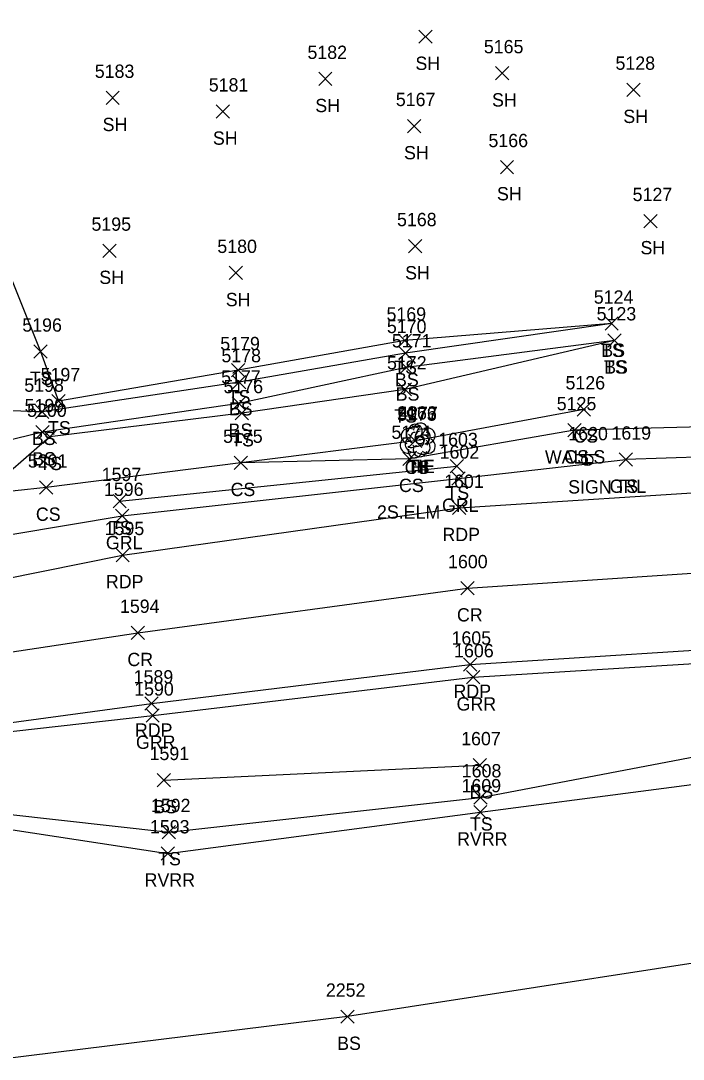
# Model space of a CAD drawing. Extents: x 1509053 to 1511576, y 400838 to 402572.
# Drawn here: x 1510102.6 to 1510202.2, y 401581.3 to 401737.4 of the extents above; entities that cross this region are included whole.
import ezdxf

# ---------------------------------------------------------------- set-up
doc = ezdxf.new("R2010")
doc.units = 0
for name, color, linetype in [('C_A', 7, 'Continuous'), ('C_I', 7, 'Continuous'), ('CBP', 7, 'Continuous'), ('L_A', 7, 'Continuous'), ('L_C', 7, 'Continuous'), ('L_I', 7, 'Continuous'), ('L_TIC', 7, 'Continuous'), ('LAWE', 7, 'Continuous'), ('LELB', 7, 'Continuous'), ('LTD', 7, 'Continuous'), ('LWS', 7, 'Continuous'), ('P_A', 7, 'Continuous'), ('P_I', 7, 'Continuous'), ('P_TIC', 7, 'Continuous'), ('PET', 7, 'Continuous'), ('PRC', 7, 'Continuous'), ('R_A', 7, 'Continuous'), ('R_I', 7, 'Continuous'), ('R_TIC', 7, 'Continuous'), ('RGR', 7, 'Continuous'), ('S_A', 7, 'Continuous'), ('S_I', 7, 'Continuous'), ('SSGN', 7, 'Continuous')]:
    doc.layers.add(name, color=color, linetype=linetype)

msp = doc.modelspace()

# ---------------------------------------------------------------- linework, layer by layer
at = {"layer": 'CBP'}
for radius in [0.625, 0.0833]:
    msp.add_circle((1510162.63, 401674.45), radius, dxfattribs=at)
at = {"layer": 'L_TIC'}
for points in [[(1510162.47, 401734.05), (1510164.47, 401736.05)], [(1510164.47, 401734.05), (1510162.47, 401736.05)], [(1510147.41, 401727.7), (1510149.41, 401729.7)], [(1510149.41, 401727.7), (1510147.41, 401729.7)], [(1510173.97, 401728.55), (1510175.97, 401730.55)], [(1510175.97, 401728.55), (1510173.97, 401730.55)], [(1510193.7, 401726.07), (1510195.7, 401728.07)], [(1510195.7, 401726.07), (1510193.7, 401728.07)], [(1510115.45, 401724.85), (1510117.45, 401726.85)], [(1510117.45, 401724.85), (1510115.45, 401726.85)], [(1510132.02, 401722.8), (1510134.02, 401724.8)], [(1510134.02, 401722.8), (1510132.02, 401724.8)], [(1510160.74, 401720.61), (1510162.74, 401722.61)], [(1510162.74, 401720.61), (1510160.74, 401722.61)], [(1510174.71, 401714.44), (1510176.71, 401716.44)], [(1510176.71, 401714.44), (1510174.71, 401716.44)], [(1510196.28, 401706.33), (1510198.28, 401708.33)], [(1510198.28, 401706.33), (1510196.28, 401708.33)], [(1510114.96, 401701.87), (1510116.96, 401703.87)], [(1510116.96, 401701.87), (1510114.96, 401703.87)], [(1510160.92, 401702.56), (1510162.92, 401704.56)], [(1510162.92, 401702.56), (1510160.92, 401704.56)], [(1510133.96, 401698.53), (1510135.96, 401700.53)], [(1510135.96, 401698.53), (1510133.96, 401700.53)], [(1510190.44, 401690.91), (1510192.44, 401692.91)], [(1510192.44, 401690.91), (1510190.44, 401692.91)], [(1510190.44, 401690.91), (1510192.44, 401692.91)], [(1510192.44, 401690.91), (1510190.44, 401692.91)], [(1510159.35, 401688.36), (1510161.35, 401690.36)], [(1510161.35, 401688.36), (1510159.35, 401690.36)], [(1510190.87, 401688.39), (1510192.87, 401690.39)], [(1510192.87, 401688.39), (1510190.87, 401690.39)], [(1510190.87, 401688.39), (1510192.87, 401690.39)], [(1510192.87, 401688.39), (1510190.87, 401690.39)], [(1510104.62, 401686.7), (1510106.62, 401688.7)], [(1510106.62, 401686.7), (1510104.62, 401688.7)], [(1510159.44, 401686.48), (1510161.44, 401688.48)], [(1510161.44, 401686.48), (1510159.44, 401688.48)], [(1510134.32, 401683.92), (1510136.32, 401685.92)], [(1510136.32, 401683.92), (1510134.32, 401685.92)], [(1510159.54, 401684.33), (1510161.54, 401686.33)], [(1510161.54, 401684.33), (1510159.54, 401686.33)], [(1510134.48, 401682.1), (1510136.48, 401684.1)], [(1510136.48, 401682.1), (1510134.48, 401684.1)], [(1510159.37, 401681.03), (1510161.37, 401683.03)], [(1510161.37, 401681.03), (1510159.37, 401683.03)], [(1510107.31, 401679.25), (1510109.31, 401681.25)], [(1510109.31, 401679.25), (1510107.31, 401681.25)], [(1510107.31, 401679.25), (1510109.31, 401681.25)], [(1510109.31, 401679.25), (1510107.31, 401681.25)], [(1510104.87, 401677.66), (1510106.87, 401679.66)], [(1510106.87, 401677.66), (1510104.87, 401679.66)], [(1510134.43, 401678.89), (1510136.43, 401680.89)], [(1510136.43, 401678.89), (1510134.43, 401680.89)], [(1510186.25, 401678.02), (1510188.25, 401680.02)], [(1510188.25, 401678.02), (1510186.25, 401680.02)], [(1510134.85, 401677.45), (1510136.85, 401679.45)], [(1510136.85, 401677.45), (1510134.85, 401679.45)], [(1510104.91, 401674.58), (1510106.91, 401676.58)], [(1510106.91, 401674.58), (1510104.91, 401676.58)], [(1510184.87, 401674.88), (1510186.87, 401676.88)], [(1510186.87, 401674.88), (1510184.87, 401676.88)], [(1510184.87, 401674.88), (1510186.87, 401676.88)], [(1510186.87, 401674.88), (1510184.87, 401676.88)], [(1510106.02, 401673.89), (1510108.02, 401675.89)], [(1510108.02, 401673.89), (1510106.02, 401675.89)], [(1510160.89, 401673.31), (1510162.89, 401675.31)], [(1510162.89, 401673.31), (1510160.89, 401675.31)], [(1510134.73, 401669.98), (1510136.73, 401671.98)], [(1510136.73, 401669.98), (1510134.73, 401671.98)], [(1510134.73, 401669.98), (1510136.73, 401671.98)], [(1510136.73, 401669.98), (1510134.73, 401671.98)], [(1510160.04, 401670.59), (1510162.04, 401672.59)], [(1510162.04, 401670.59), (1510160.04, 401672.59)], [(1510192.59, 401670.47), (1510194.59, 401672.47)], [(1510194.59, 401670.47), (1510192.59, 401672.47)], [(1510167.19, 401669.5), (1510169.19, 401671.5)], [(1510169.19, 401669.5), (1510167.19, 401671.5)], [(1510105.47, 401666.26), (1510107.47, 401668.26)], [(1510107.47, 401666.26), (1510105.47, 401668.26)], [(1510116.5, 401664.24), (1510118.49, 401666.24)], [(1510118.49, 401664.24), (1510116.5, 401666.24)], [(1510170.63, 401624.52), (1510172.63, 401626.52)], [(1510172.63, 401624.52), (1510170.63, 401626.52)], [(1510123.12, 401622.29), (1510125.12, 401624.29)], [(1510125.12, 401622.29), (1510123.12, 401624.29)], [(1510170.73, 401619.69), (1510172.73, 401621.69)], [(1510172.73, 401619.69), (1510170.73, 401621.69)], [(1510170.7, 401617.45), (1510172.7, 401619.45)], [(1510172.7, 401617.45), (1510170.7, 401619.45)], [(1510123.88, 401614.47), (1510125.88, 401616.47)], [(1510125.88, 401614.47), (1510123.88, 401616.47)], [(1510123.74, 401611.27), (1510125.74, 401613.27)], [(1510125.74, 401611.27), (1510123.74, 401613.27)], [(1510150.75, 401586.72), (1510152.75, 401588.72)], [(1510152.75, 401586.72), (1510150.75, 401588.72)]]:
    msp.add_lwpolyline(points, dxfattribs=at)
at = {"layer": 'LAWE'}
msp.add_lwpolyline([(1510071.34, 401620.03), (1510084.03, 401618.47), (1510124.74, 401612.27), (1510171.7, 401618.45), (1510222.28, 401625.1), (1510269.32, 401619.28), (1510308.65, 401601.1)], dxfattribs=at)
at = {"layer": 'LELB'}
for points in [[(1510118.99, 401826.89), (1510108.76, 401803.89), (1510097.32, 401781.18), (1510092.53, 401751.99), (1510094.65, 401729.03), (1510099.12, 401703.69), (1510105.62, 401687.7), (1510108.31, 401680.25)], [(1510431.72, 401516.61), (1510341.14, 401547.81), (1510292.56, 401583.77), (1510226.42, 401599.28), (1510151.75, 401587.72), (1510095.68, 401580.81), (1510017.56, 401603.54), (1510015.48, 401644.92), (1509989.35, 401675.01), (1509940.27, 401707.21)], [(1510191.44, 401691.91), (1510160.44, 401687.48), (1510135.48, 401683.1), (1510105.87, 401678.66), (1510096.16, 401678.94), (1510084.48, 401675.13), (1510076.18, 401668.6)], [(1510191.44, 401691.91), (1510160.35, 401689.36), (1510135.32, 401684.92), (1510108.31, 401680.25)], [(1510191.87, 401689.39), (1510160.54, 401685.33), (1510135.43, 401679.89), (1510105.91, 401675.58), (1510095.98, 401673.19), (1510085.95, 401670.54), (1510076.18, 401668.6)], [(1510191.87, 401689.39), (1510160.37, 401682.03), (1510135.85, 401678.45), (1510107.02, 401674.89), (1510097.1, 401666.29)], [(1510187.25, 401679.02), (1510161.89, 401674.31), (1510135.73, 401670.98)], [(1510185.87, 401675.88), (1510161.04, 401671.59), (1510135.73, 401670.98), (1510106.47, 401667.26), (1510097.1, 401666.29), (1510085.95, 401670.54)], [(1510211.76, 401672.09), (1510193.59, 401671.47)], [(1510117.5, 401665.24), (1510168.19, 401670.5)], [(1510171.73, 401620.69), (1510221.35, 401630.16)], [(1510124.12, 401623.29), (1510171.63, 401625.52)], [(1510071.52, 401621.36), (1510084.05, 401620.01), (1510124.88, 401615.47)], [(1510124.88, 401615.47), (1510171.73, 401620.69)]]:
    msp.add_lwpolyline(points, dxfattribs=at)
at = {"layer": 'LTD'}
for p, q in [((1510161.89, 401674.31), (1510161.89, 401674.31)), ((1510161.89, 401674.31), (1510161.89, 401674.31)), ((1510162.65, 401674.48), (1510162.65, 401674.48)), ((1510162.65, 401674.48), (1510162.65, 401674.48))]:
    msp.add_line(p, q, dxfattribs=at)
for centre in [(1510161.93, 401675.74), (1510162.7, 401675.91)]:
    msp.add_arc(centre, 1.05, 335.5272, 180.9563, dxfattribs=at)
for centre, major_axis, ratio, start_param, end_param in [((1510161.86, 401675.14), (1.21, -0.51), 0.895232, 1.570796, 4.712389), ((1510161.09, 401674.97), (1.21, -0.51), 0.895232, 1.570796, 4.712389), ((1510161.68, 401674.77), (-0.208, -0.792), 0.645439, 3.141593, 6.283185), ((1510162.44, 401674.93), (-0.208, -0.792), 0.645439, 3.141593, 6.283185), ((1510162.39, 401674.14), (-0.5, 0.667), 0.989748, 3.141593, 6.283185), ((1510162.93, 401674.89), (-1.14, -0.48), 0.949671, 1.570796, 4.712389), ((1510163.15, 401674.31), (-0.5, 0.667), 0.989748, 3.141593, 6.283185), ((1510163.69, 401675.06), (-1.14, -0.48), 0.949671, 1.570796, 4.712389), ((1510160.8, 401673.6), (0.58, -1.04), 0.959034, 3.141593, 6.283185), ((1510161.57, 401673.77), (0.58, -1.04), 0.959034, 3.141593, 6.283185), ((1510161.43, 401673.56), (-0.625, -0.083), 0.423636, 0, 3.141593), ((1510162.19, 401673.73), (-0.625, -0.083), 0.423636, 0, 3.141593), ((1510162.89, 401673.47), (-1.09, 0.79), 0.841452, 1.570796, 4.712389), ((1510163.65, 401673.64), (-1.09, 0.79), 0.841452, 1.570796, 4.712389), ((1510161.89, 401672.81), (0.26, 1.06), 0.942809, 1.570796, 4.712389), ((1510162.65, 401672.98), (0.26, 1.06), 0.942809, 1.570796, 4.712389)]:
    msp.add_ellipse(centre, major_axis=major_axis, ratio=ratio, start_param=start_param, end_param=end_param, dxfattribs=at)
at = {"layer": 'LWS'}
msp.add_lwpolyline([(1510349.81, 401679.3), (1510337.11, 401685.04), (1510331.2, 401679.18), (1510316.95, 401676.48), (1510297.59, 401679.14), (1510269.51, 401678.15), (1510244.84, 401677.73), (1510225.49, 401677.12), (1510218.49, 401676.76), (1510185.87, 401675.88)], dxfattribs=at)
at = {"layer": 'P_TIC'}
for points in [[(1510167.51, 401663.21), (1510169.51, 401665.21)], [(1510169.51, 401663.21), (1510167.51, 401665.21)], [(1510116.95, 401656.12), (1510118.95, 401658.12)], [(1510118.95, 401656.12), (1510116.95, 401658.12)], [(1510168.76, 401651.13), (1510170.76, 401653.13)], [(1510170.76, 401651.13), (1510168.76, 401653.13)], [(1510119.23, 401644.42), (1510121.23, 401646.42)], [(1510121.23, 401644.42), (1510119.23, 401646.42)], [(1510169.19, 401639.65), (1510171.19, 401641.65)], [(1510171.19, 401639.65), (1510169.19, 401641.65)], [(1510121.3, 401633.81), (1510123.3, 401635.81)], [(1510123.3, 401633.81), (1510121.3, 401635.81)]]:
    msp.add_lwpolyline(points, dxfattribs=at)
at = {"layer": 'PET'}
for points in [[(1510068.52, 401654.76), (1510069.7, 401647.38), (1510117.95, 401657.12), (1510168.51, 401664.21), (1510212.05, 401667), (1510220.39, 401667.36), (1510271.44, 401667.79), (1510321.9, 401665.44), (1510371.76, 401662.64), (1510420.35, 401661.34), (1510470.43, 401662.43), (1510520.33, 401664.72), (1510570.63, 401667.06), (1510593.1, 401669.05), (1510621.58, 401670.53), (1510656.11, 401672.66)], [(1510069.7, 401647.38), (1510070.82, 401637.95), (1510072.41, 401628.04), (1510122.3, 401634.81), (1510170.19, 401640.65), (1510220.23, 401643.86), (1510269.72, 401644.29), (1510320.63, 401641.42), (1510370.24, 401637.87), (1510421.73, 401637.03), (1510472.3, 401638.25), (1510523.24, 401640.81), (1510571.7, 401643.53), (1510622.45, 401646.41), (1510672.72, 401649.13), (1510722.86, 401651.91), (1510723.41, 401651.94), (1510773.15, 401654.37), (1510822.4, 401657.74), (1510872.35, 401660.8), (1510922.85, 401663.95), (1510967.23, 401666.49), (1511034, 401670.65), (1511071.49, 401673.22)]]:
    msp.add_lwpolyline(points, dxfattribs=at)
at = {"layer": 'PRC'}
msp.add_lwpolyline([(1510070.82, 401637.95), (1510120.23, 401645.42), (1510169.76, 401652.13), (1510220.07, 401655.52), (1510220.14, 401655.43), (1510270.51, 401655.53), (1510320.84, 401653.34), (1510371.03, 401650.53), (1510421.26, 401649.11), (1510471.33, 401650.1), (1510521.34, 401652.38), (1510571.58, 401655.12), (1510621.67, 401657.75), (1510671.66, 401660.66), (1510722.15, 401663.46), (1510772.15, 401666.42), (1510822.28, 401669.1), (1510872.26, 401671.98), (1510872.29, 401672.01), (1510922.21, 401674.96), (1510971.31, 401678.08), (1511022.51, 401681.61), (1511070.2, 401684.98)], dxfattribs=at)
at = {"layer": 'R_TIC'}
for points in [[(1510192.59, 401670.47), (1510194.59, 401672.47)], [(1510194.59, 401670.47), (1510192.59, 401672.47)], [(1510167.4, 401667.61), (1510169.4, 401669.61)], [(1510169.4, 401667.61), (1510167.4, 401669.61)], [(1510116.88, 401662), (1510118.88, 401664)], [(1510118.88, 401662), (1510116.88, 401664)], [(1510169.64, 401637.74), (1510171.64, 401639.74)], [(1510171.64, 401637.74), (1510169.64, 401639.74)], [(1510121.46, 401631.98), (1510123.46, 401633.98)], [(1510123.46, 401631.98), (1510121.46, 401633.98)]]:
    msp.add_lwpolyline(points, dxfattribs=at)
at = {"layer": 'RGR'}
for points in [[(1510068.52, 401654.76), (1510117.89, 401663), (1510168.4, 401668.61), (1510193.59, 401671.47)], [(1510073.99, 401627.51), (1510122.46, 401632.98), (1510170.64, 401638.74), (1510220.08, 401641.84), (1510269.6, 401641.85), (1510311.11, 401639.49), (1510334.05, 401636.42), (1510370.16, 401634.91), (1510403.15, 401632.59)]]:
    msp.add_lwpolyline(points, dxfattribs=at)
at = {"layer": 'SSGN'}
for p, q in [((1510186.12, 401672.23), (1510189.45, 401672.23)), ((1510187.77, 401671.39), (1510187.77, 401671.39))]:
    msp.add_line(p, q, dxfattribs=at)
msp.add_circle((1510187.77, 401671.39), 0.833, dxfattribs=at)

# ---------------------------------------------------------------- texts
at = {"layer": 'C_A'}
msp.add_text('TIE', height=2, dxfattribs=at).set_placement((1510160.71, 401669.45))
at = {"layer": 'C_I'}
msp.add_text('4277', height=2, dxfattribs=at).set_placement((1510159.37, 401677.45))
at = {"layer": 'L_A'}
for s, p in [('SH', (1510161.95, 401730.05)), ('SH', (1510173.46, 401724.55)), ('SH', (1510146.9, 401723.7)), ('SH', (1510193.19, 401722.07)), ('SH', (1510114.94, 401720.85)), ('SH', (1510131.51, 401718.8)), ('SH', (1510160.23, 401716.61)), ('SH', (1510174.2, 401710.44)), ('SH', (1510195.77, 401702.33)), ('SH', (1510114.44, 401697.87)), ('SH', (1510160.4, 401698.56)), ('SH', (1510133.45, 401694.53)), ('TS', (1510189.85, 401686.91)), ('BS', (1510189.88, 401686.91)), ('TS', (1510158.76, 401684.36)), ('TS', (1510190.28, 401684.39)), ('BS', (1510190.31, 401684.39)), ('TS', (1510104.03, 401682.7)), ('BS', (1510158.88, 401682.48)), ('TS', (1510133.73, 401679.92)), ('BS', (1510158.98, 401680.33)), ('BS', (1510133.92, 401678.1)), ('TS', (1510158.78, 401677.03)), ('TS', (1510106.72, 401675.25)), ('TS', (1510106.72, 401675.25)), ('BS', (1510133.87, 401674.89)), ('BS', (1510104.31, 401673.66)), ('TS', (1510134.26, 401673.45)), ('CS', (1510185.69, 401674.02)), ('BS', (1510104.35, 401670.58)), ('TS', (1510105.42, 401669.89)), ('WALLS', (1510181.41, 401670.88)), ('CS', (1510184.31, 401670.88)), ('CS', (1510160.33, 401669.31)), ('H', (1510161.32, 401669.31)), ('H', (1510162.08, 401669.48)), ('CS', (1510134.17, 401665.98)), ('CS', (1510134.17, 401665.98)), ('CS', (1510159.48, 401666.59)), ('TS', (1510166.6, 401665.5)), ('TS', (1510192, 401666.47)), ('CS', (1510104.91, 401662.26)), ('TS', (1510115.9, 401660.24)), ('BS', (1510170.07, 401620.52)), ('BS', (1510122.56, 401618.29)), ('TS', (1510170.14, 401615.69)), ('RVRR', (1510168.21, 401613.45)), ('TS', (1510123.29, 401610.47)), ('RVRR', (1510121.25, 401607.27)), ('BS', (1510150.19, 401582.72))]:
    msp.add_text(s, height=2, dxfattribs=at).set_placement(p)
at = {"layer": 'L_C'}
msp.add_text('2S.ELM', height=2, dxfattribs=at).set_placement((1510156.17, 401662.59))
at = {"layer": 'L_I'}
for s, p in [('5165', (1510172.23, 401732.55)), ('5182', (1510145.72, 401731.7)), ('5128', (1510192.01, 401730.07)), ('5183', (1510113.76, 401728.85)), ('5181', (1510130.89, 401726.8)), ('5167', (1510159, 401724.61)), ('5166', (1510172.92, 401718.44)), ('5127', (1510194.59, 401710.33)), ('5195', (1510113.26, 401705.87)), ('5168', (1510159.18, 401706.56)), ('5180', (1510132.18, 401702.53)), ('5124', (1510188.75, 401694.91)), ('5124', (1510188.75, 401694.91)), ('5169', (1510157.6, 401692.36)), ('5123', (1510189.18, 401692.39)), ('5123', (1510189.18, 401692.39)), ('5196', (1510102.87, 401690.7)), ('5170', (1510157.66, 401690.48)), ('5179', (1510132.62, 401687.92)), ('5171', (1510158.41, 401688.33)), ('5178', (1510132.79, 401686.1)), ('5172', (1510157.68, 401685.03)), ('5197', (1510105.62, 401683.25)), ('5197', (1510105.62, 401683.25)), ('5177', (1510132.74, 401682.89)), ('5198', (1510103.17, 401681.66)), ('5176', (1510133.1, 401681.45)), ('5126', (1510184.5, 401682.02)), ('5199', (1510103.21, 401678.58)), ('5200', (1510103.59, 401677.89)), ('5125', (1510183.18, 401678.88)), ('5125', (1510183.18, 401678.88)), ('5173', (1510159.19, 401677.31)), ('5173', (1510159.19, 401677.31)), ('2066', (1510159.21, 401677.48)), ('5174', (1510158.34, 401674.59)), ('1619', (1510191.41, 401674.47)), ('5175', (1510133.04, 401673.98)), ('5175', (1510133.04, 401673.98)), ('1603', (1510165.37, 401673.5)), ('5201', (1510103.7, 401670.26)), ('1597', (1510114.8, 401668.24)), ('1607', (1510168.82, 401628.52)), ('1591', (1510121.99, 401626.29)), ('1608', (1510168.91, 401623.69)), ('1609', (1510168.87, 401621.45)), ('1592', (1510122.19, 401618.47)), ('1593', (1510122.05, 401615.27)), ('2252', (1510148.49, 401590.72))]:
    msp.add_text(s, height=2, dxfattribs=at).set_placement(p)
at = {"layer": 'P_A'}
for s, p in [('RDP', (1510166, 401659.21)), ('RDP', (1510115.43, 401652.12)), ('CR', (1510168.19, 401647.13)), ('CR', (1510118.66, 401640.42)), ('RDP', (1510167.67, 401635.65)), ('RDP', (1510119.79, 401629.81))]:
    msp.add_text(s, height=2, dxfattribs=at).set_placement(p)
at = {"layer": 'P_I'}
for s, p in [('1601', (1510166.26, 401667.21)), ('1595', (1510115.25, 401660.12)), ('1600', (1510166.85, 401655.13)), ('1594', (1510117.54, 401648.42)), ('1605', (1510167.37, 401643.65)), ('1589', (1510119.6, 401637.81))]:
    msp.add_text(s, height=2, dxfattribs=at).set_placement(p)
at = {"layer": 'R_A'}
for s, p in [('GRL', (1510191.13, 401666.47)), ('GRL', (1510165.94, 401663.61)), ('GRL', (1510115.43, 401658)), ('GRR', (1510168.13, 401633.74)), ('GRR', (1510119.95, 401627.98))]:
    msp.add_text(s, height=2, dxfattribs=at).set_placement(p)
at = {"layer": 'R_I'}
for s, p in [('1619', (1510191.41, 401674.47)), ('1602', (1510165.58, 401671.61)), ('1596', (1510115.14, 401666)), ('1606', (1510167.76, 401641.74)), ('1590', (1510119.68, 401635.98))]:
    msp.add_text(s, height=2, dxfattribs=at).set_placement(p)
at = {"layer": 'S_A'}
msp.add_text('SIGN', height=2, dxfattribs=at).set_placement((1510184.9, 401666.37))
at = {"layer": 'S_I'}
msp.add_text('1620', height=2, dxfattribs=at).set_placement((1510184.92, 401674.37))

doc.saveas('drawing.dxf')
